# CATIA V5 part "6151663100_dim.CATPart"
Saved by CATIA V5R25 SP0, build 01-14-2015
Part number: 6151663100_dim
Source: made
Property "PROI_CREATED_ON": "12/17/2008 9:21:37 AM"
Property "BLANK_DRAWING": "--"
Property "DRAWN_BY": "ALG"
Property "FINISH": "--"
Property "HEAT_TREATMENT": "ASSIGN"
Property "MATERIAL": "ASSIGN"
Property "PROJECT": "--"
Property "PROTOTYPE_NO": "--"
Property "RELATED_DRAWING": "--"
Property "COMPLETE_MATERIAL": "ASSIGN-ASSIGN"
Property "DESCRIPTION": "EPD70-850-SQ1/2-5"
Property "DRAWING_EXIST": "--"
Property "MANUFACTURER": "--"
Property "MANUFACTURER_2": "--"
Property "MANUFACTURER_REF": "--"
Property "TYPE_PART": "A"
Property "TODAY_DATE": "2023/08/11"
Property "MFG_WP_MATERIAL": "ASSIGN"
Property "COMPANY_CODE": "---"
Property "DESCRIPTION_JP": "--"
Property "PQP_DOCUMENT": "--"
Property "SUPPLIER": "--"
Property "REFERENCE": "6151663100"
Property "PTC_WM_REVISION": "01"
Property "PTC_WM_ITERATION": "0"
Property "PTC_WM_VERSION": "01.0"
Property "PTC_WM_LIFECYCLE_STATE": "Production"
Property "PTC_WM_LIFECYCLE": "Design_Process"
Property "PTC_WM_LOCATION": "/Products/ELECTRIC EB TOOLS/A1760 - CORDED PISTOL NUTRUNNER/9-01-Dimensional Dra"
Property "PTC_WM_CREATED_BY": "Alain Le Goc (grealg) (grealg: CPD)"
Property "PTC_WM_CREATED_ON": "11-Aug-23 09:28:30 AM"
Property "PTC_WM_MODIFIED_BY": "Alain Le Goc (grealg) (grealg: CPD)"
Property "PTC_WM_MODIFIED_ON": "11-Aug-23 11:23:24 AM"
Property "PTC_WM_TEAM": "Default"
Property "PTC_ORGANIZATION_ID": "CPD"
Property "EXPORT_CONTROL": "NULL"
Property "PTC_WM_NAME": "6151663100_dim.prt"
Property "PTC_WM_NUMBER": "6151663100_DIM.PRT"
Property "PTC_MODIFIED": false
Property "PDMREV": "01.0"
Property "PDMRL": "Production"
Property "PROI_REVISION": "01"
Property "PROI_VERSION": "0"
Property "PROI_RELEASE": "Production"
Property "PTC_COMMON_NAME": "6151663100_dim.prt"
Property "PTC_MASTER_MATERIAL": "ASSIGN"
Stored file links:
  d:\ptc\Echange\temp\6151663100_dim.CATPart

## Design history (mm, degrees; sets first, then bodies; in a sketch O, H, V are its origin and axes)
AxisSystem1 "CS0": origin (0, 0, 0), X (1, 0, 0), Y (0, 1, 0), Z (0, 0, 1)
Set1
  DatumSurface1 "Sheet.1"
  DatumSurface2 "Sheet.2"
  DatumSurface3 "Sheet.3"
  DatumSurface4 "Sheet.4"
  DatumSurface5 "Sheet.5"
  DatumSurface6 "Sheet.6"
  DatumSurface7 "Sheet.7"
  DatumSurface8 "Sheet.8"
  DatumSurface9 "Sheet.9"
  DatumSurface10 "Sheet.10"
  DatumSurface11 "Sheet.11"
  DatumSurface12 "Sheet.12"
  DatumSurface13 "Sheet.13"
  DatumSurface14 "Sheet.14"
  DatumSurface15 "Sheet.15"
  DatumSurface16 "Sheet.16"
  DatumSurface17 "Sheet.17"
  DatumSurface18 "Sheet.18"
  DatumSurface19 "Sheet.19"
  DatumSurface20 "Sheet.20"
  DatumSurface21 "Sheet.21"
  DatumSurface22 "Sheet.22"
  DatumSurface23 "Sheet.23"
  DatumSurface24 "Sheet.24"
  DatumSurface25 "Sheet.25"
  DatumSurface26 "Sheet.26"
  DatumSurface27 "Sheet.27"
  DatumSurface28 "Sheet.28"
  DatumSurface29 "Sheet.29"
  DatumSurface30 "Sheet.30"
  DatumSurface31 "Sheet.31"
  DatumSurface32 "Sheet.32"
  DatumSurface33 "Sheet.33"
  DatumSurface34 "Sheet.34"
  DatumSurface35 "Sheet.35"
  DatumSurface36 "Sheet.36"
  DatumSurface37 "Sheet.37"
  DatumSurface38 "Sheet.38"
  DatumSurface39 "Sheet.39"
  DatumSurface40 "Sheet.40"
  DatumSurface41 "Sheet.41"
  DatumSurface42 "Sheet.42"
  DatumSurface43 "Sheet.43"
  DatumSurface44 "Sheet.44"
  DatumSurface45 "Sheet.45"
  DatumSurface46 "Sheet.46"
  DatumSurface47 "Sheet.47"
  DatumSurface48 "Sheet.48"
  DatumSurface49 "Sheet.49"
  DatumSurface50 "Sheet.50"
  DatumSurface51 "Sheet.51"
  DatumSurface52 "Sheet.52"
  DatumSurface53 "Sheet.53"
  DatumSurface54 "Sheet.54"
  DatumSurface55 "Sheet.55"
  DatumSurface56 "Sheet.56"
  DatumSurface57 "Sheet.57"
  DatumSurface58 "Sheet.58"
  DatumSurface59 "Sheet.59"
  DatumSurface60 "Sheet.60"
  DatumSurface61 "Sheet.61"
  DatumSurface62 "Sheet.62"
  DatumSurface63 "Sheet.63"
  DatumSurface64 "Sheet.64"
  DatumSurface65 "Sheet.65"
  DatumSurface66 "Sheet.66"
  DatumSurface67 "Sheet.67"
  DatumSurface68 "Sheet.68"
  DatumSurface69 "Sheet.69"
  DatumSurface70 "Sheet.70"
  DatumSurface71 "Sheet.71"
  DatumSurface72 "Sheet.72"
  DatumSurface73 "Sheet.73"
  DatumSurface74 "Sheet.74"
  DatumSurface75 "Sheet.75"
  DatumSurface76 "Sheet.76"
  DatumSurface77 "Sheet.77"
  DatumSurface78 "Sheet.78"
  DatumSurface79 "Sheet.79"
  DatumSurface80 "Sheet.80"
  DatumSurface81 "Sheet.81"
  DatumSurface82 "Sheet.82"
  DatumSurface83 "Sheet.83"
  DatumSurface84 "Sheet.84"
  Plane1 "RIGHT": stored without definition
  Plane2 "TOP": stored without definition
  Plane3 "FRONT": stored without definition
Body1 "PartBody" (main body)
